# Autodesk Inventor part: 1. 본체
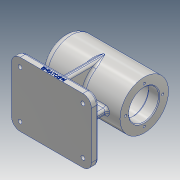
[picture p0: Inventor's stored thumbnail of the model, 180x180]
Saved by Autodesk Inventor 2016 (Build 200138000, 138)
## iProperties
Created: 2020-10
Part Number: 1. 본체
Material: 알루미늄 6061
Document SubType Name: Modeling
Designer: user
Density: 2.7 g/cm^3
Appearance: 알루미늄 - 평지
Mass: 1026.28 g
Surface Area: 757.984 cm^2
Volume: 380.103 cm^3
Author: user
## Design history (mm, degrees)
sketch "스케치1"
  geometry: L1 (0, 0)-(112, 0); L2 (0, 0)-(0, 34); L3 (0, 34)-(112, 34); L4 (112, 34)-(112, 0); L5 (6, 0)-(6, 10.5); L6 (6, 10.5)-(9, 10.5); L7 (9, 10.5)-(9, 16); L8 (9, 16)-(13, 16); L9 (13, 16)-(13, 17.5); L10 (13, 17.5)-(31, 17.5); L11 (31, 17.5)-(31, 21); L12 (31, 21)-(43, 21); L13 (43, 21)-(43, 24); L14 (43, 24)-(97, 24); L15 (97, 24)-(97, 21); L16 (97, 21)-(112, 21)
  constraints: 32 end point, 9 perpendicular, 4 point on line, 4 vertical, 2 horizontal
  dimensions: "d0" = 112 distance of L1.start L1.end; "d1" = 42 diameter of L16 L1; "d2" = 48 diameter of L14 L1; "d3" = 35 diameter of L10 L1; "d4" = 32 diameter of L8 L1; "d5" = 21 diameter of L6 L1; "d6" = 15 distance of L15.end L16.end; "d7" = 54 distance of L13.end L14.end; "d8" = 12 distance of L11.end L12.end; "d9" = 18 distance of L9.end L10.end; "d10" = 4 distance of L7.end L8.end; "d11" = 3 distance of L5.end L6.end; "d12" = 68 diameter of L3 L1
revolve "회전1" sketch "스케치1" stored, may be unused: angle "d13" = 90 deg
fillet "모깎기1" dims "d14" = 0.3
fillet "모깎기2" dims "d15" = 3
fillet "모깎기3" dims "d16" = 10
chamfer "모따기1" distance "d17" = 1; stored, may be unused: second distance "d18" = 2, angle "d19" = 45 deg
sketch "스케치2"
  geometry: L1 (-45, -64)-(45, -64); L2 (45, -64)-(45, -74); L3 (45, -74)-(-45, -74); L4 (-45, -74)-(-45, -64); 2 further points
  constraints: 8 end point, 2 parallel, 1 horizontal, 1 midpoint, 1 perpendicular, 1 vertical alignment
  dimensions: "d20" = 90 distance of L2.end L3.end; "d21" = 10 distance of L1.end L2.end; "d22" = 74 distance from line of L3 point (0, 0)
extrude "돌출1" join sketch "스케치2" distance "d23" = 112; taper "d24" = 0 deg
sketch "스케치3"
  geometry: L1 (-60, 79)-(-52, 79); L2 (-52, 79)-(-52, 11); L3 (-52, 11)-(-60, 11); L4 (-60, 11)-(-60, 79); L5 (0, 90)-(-112, 90) reference; L6 (0, 90)-(0, 0) reference; 4 further points
  constraints: 8 end point, 3 midpoint, 2 parallel, 1 horizontal, 1 horizontal alignment, 1 perpendicular, 1 vertical alignment
  dimensions: "d25" = 8 distance of L1.start L1.end; "d26" = 68 distance of L1.end L2.end
extrude "돌출2" join sketch "스케치3" stored distance "d27" = 112; taper "d28" = 0 deg
sketch "스케치4"
  geometry: L1 (10, -34)-(112, -34) reference; L2 (112, -64)-(0, -64) reference; L3 (18, -34)-(18, -64); L4 (112, -64)-(0, -64) reference; L5 (0, -64)-(0, -74) reference; 1 further point
  constraints: 2 end point, 2 point on line, 1 perpendicular
  dimensions: "d29" = 18 distance between parallel lines of L3 L5
feature "리브1" sketch "스케치4" dims "d30" = 1, "d31" = 8, "d32" = 0, "d33" = 0, "d34" = 1, "d35" = 1
node "작업 평면1"
fillet "모깎기4" dims "d36" = 12
fillet "모깎기5" dims "d37" = 3
fillet "모깎기6" dims "d38" = 3
sketch "스케치5"
  geometry: 2 further points
  constraints: 1 vertical alignment
  dimensions: "d39" = 26 distance of point (0, 0) point (0, 26)
hole "구멍1" sketch "스케치5" at (0, 26) diameter "d40" = 3.242; stored, may be unused: countersink angle "d44" = 90 deg, drill point angle "d46" = 118 deg; dims "d41" = 8, "d42" = 4, "d43" = 2, "d45" = 11
sketch "스케치6"
  geometry: A1 r 12 centre (0, 75) between (0, 87) and (-12, 75) reference; A2 r 12 centre (88, 75) between (100, 75) and (88, 87) reference; A3 r 12 centre (88, 9) between (88, -3) and (100, 9) reference; A4 r 12 centre (0, 9) between (-12, 9) and (0, -3) reference; 1 further point
hole "구멍2" sketch "스케치6" at (0, 75), (0, 9), (88, 9), (88, 75) diameter "d50" = 5.5; stored, may be unused: countersink angle "d54" = 90 deg, drill point angle "d56" = 118 deg; dims "d51" = 8, "d52" = 9.5, "d53" = 5.4, "d55" = 11
sketch "스케치7"
  geometry: L1 (27.408, 5.402)-(60.592, 5.402); L2 (60.592, 5.402)-(60.592, 0.598); L3 (60.592, 0.598)-(27.408, 0.598); L4 (27.408, 0.598)-(27.408, 5.402); L5 (27.408, 3)-(44, 3); L6 (44, 3)-(44, 5.402); L7 (100, 0)-(100, 7) reference; L8 (88, 0)-(0, 0) reference; 1 further point
  constraints: 4 end point, 2 midpoint, 1 horizontal, 2 other
  dimensions: "d57" = 56 distance from line of L7 L5.end; "d58" = 3 distance from line of L8 L5.end
feature "엠보싱1" sketch "스케치7" dims "d0" = 112, "d1" = 42, "d2" = 48, "d3" = 35, "d4" = 32, "d5" = 21, "d6" = 15, "d7" = 54, "d8" = 12, "d9" = 18, "d10" = 4, "d11" = 3, "d12" = 68, "d59" = 0.5, "d60" = 0
node "솔리드1"
mirror "대칭1"
pattern_circular "원형 패턴1" dims angle "d48" = 360 deg
